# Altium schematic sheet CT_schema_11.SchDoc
size 382 x 278 mm
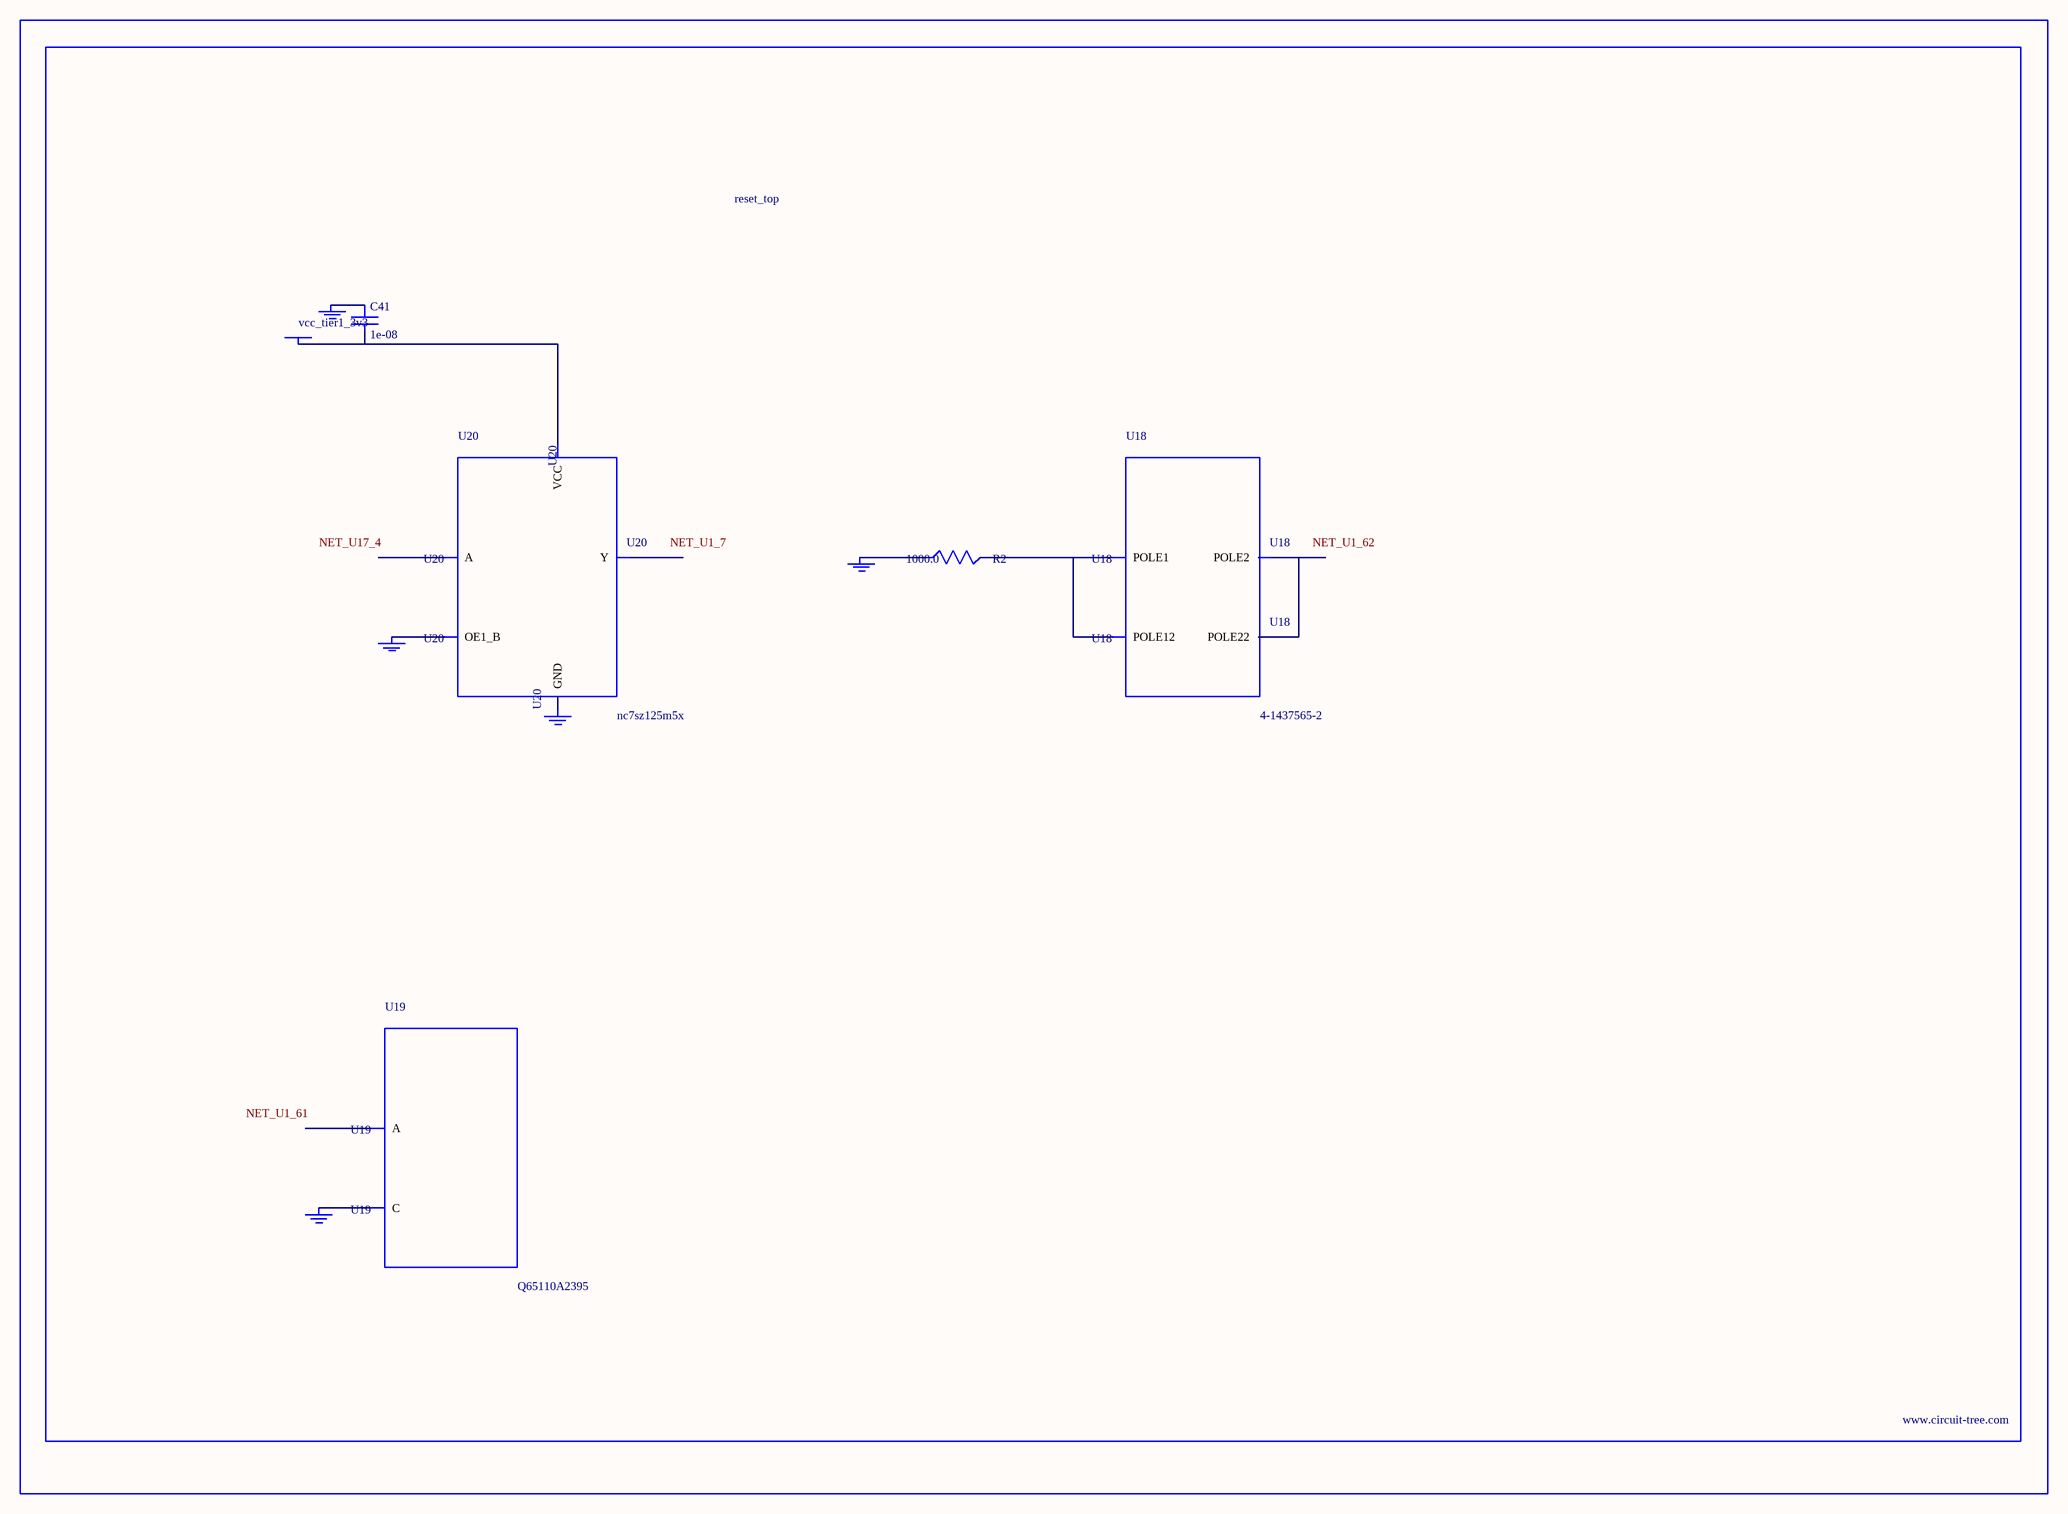
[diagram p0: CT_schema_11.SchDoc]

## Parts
BORDER10  (no value)
C41  1e-08  [C0402]
GND_INSTANCE_10_0  (no value)
GND_INSTANCE_10_1  (no value)
GND_INSTANCE_10_2  (no value)
GND_INSTANCE_10_3  (no value)
GND_INSTANCE_10_4  (no value)
POWER_INSTANCE_10_0  vcc_tier1_3v3
R2  1000.0  [R0603]
U18  4-1437565-2  [SW_4-1437565-2]
U19  Q65110A2395  [LGM67K-G1J2-24-Z]
U20  nc7sz125m5x  [NC7SZ125M5X]

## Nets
NetC41_1: C41.1 GND_INSTANCE_10_2.0(GND)
NetC41_2: C41.2 POWER_INSTANCE_10_0.0(PWR) U20.5(VCC)
NetGND_INSTANCE_10_0_0: GND_INSTANCE_10_0.0(GND) R2.1
NetGND_INSTANCE_10_1_0: GND_INSTANCE_10_1.0(GND) U19.C
NetGND_INSTANCE_10_3_0: GND_INSTANCE_10_3.0(GND) U20.1(OE1_B)
NetGND_INSTANCE_10_4_0: GND_INSTANCE_10_4.0(GND) U20.3(GND)
NetR2_2: R2.2 U18.1(POLE1) U18.2(POLE12)
NetU18_3: U18.3(POLE2) U18.4(POLE22)

Not connected (* = marked no-connect by the designer): U19 A; U20 2(A) 4(Y)

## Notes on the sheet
- Labels drawn without touching a wire or pin: NET_U1_7, NET_U1_61, NET_U1_62, NET_U17_4

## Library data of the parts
BORDER10 = BORDER_PAGE10
C41 = C0402C103K3RAC
GND_INSTANCE_10_0-GND_INSTANCE_10_4 = GND
POWER_INSTANCE_10_0 = PWR
R2 = RC0603JR-071KL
